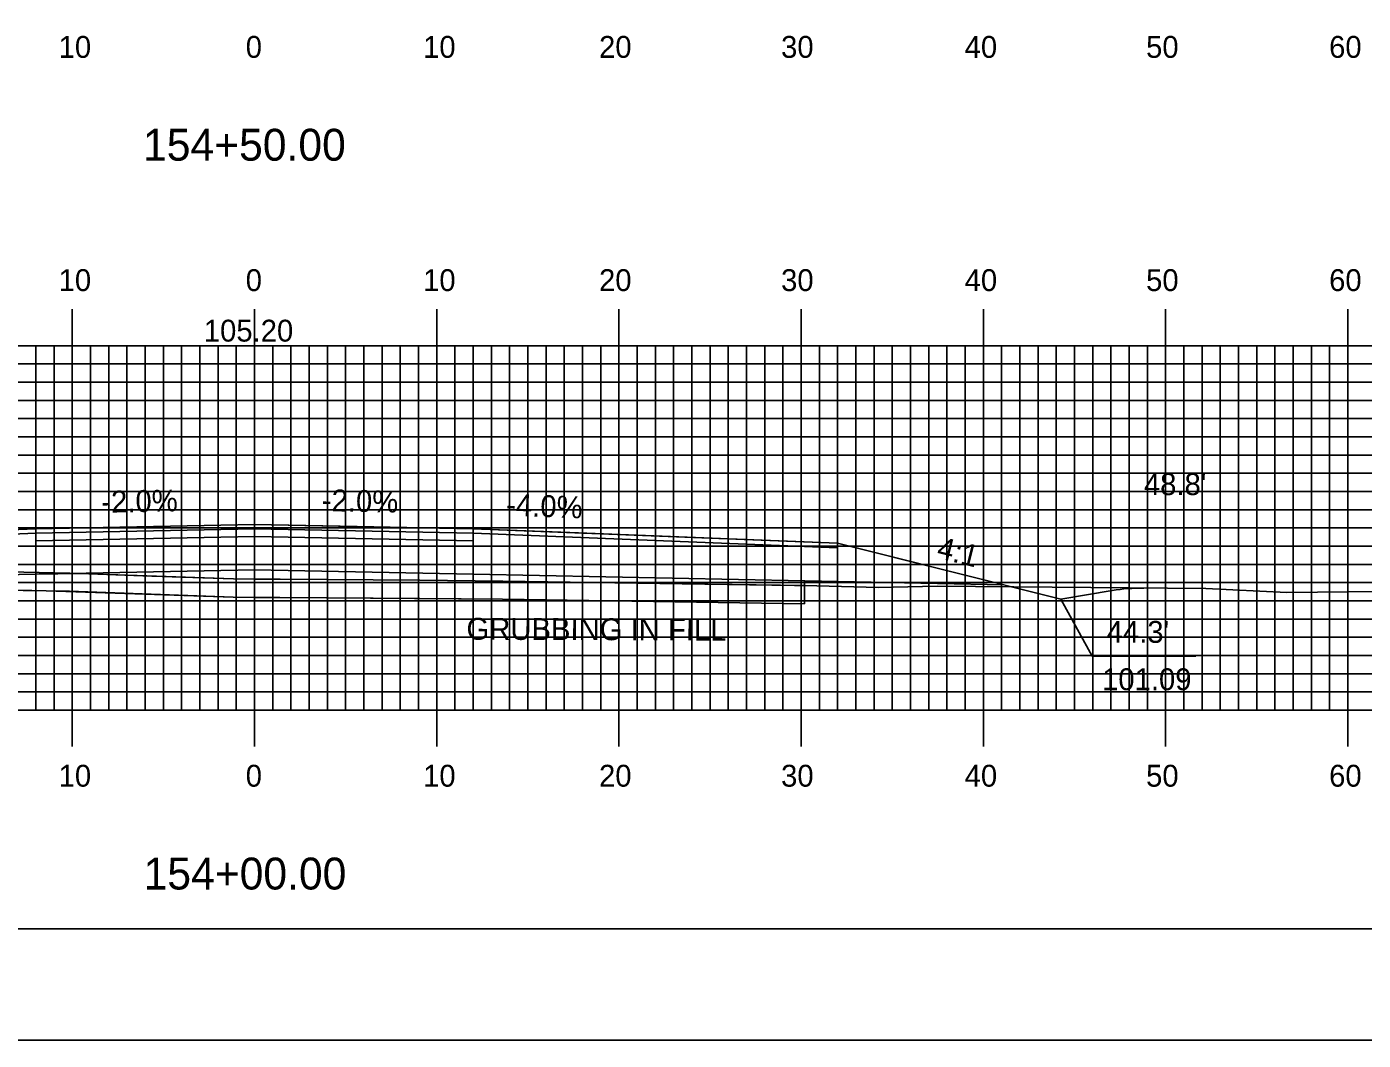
# Model space of a CAD drawing. Extents: x 1779106 to 1779449, y 442591 to 442811.
# Drawn here: x 1779258.8 to 1779332.2, y 442590.5 to 442646.2 of the extents above; entities that cross this region are included whole.
import ezdxf

# ---------------------------------------------------------------- set-up
doc = ezdxf.new("R2010")
doc.units = 0
for name, color, linetype in [('ANNOTATION', 7, 'Continuous'), ('BORDER', 7, 'Continuous'), ('D_Roadway_Centerline', 7, 'Continuous'), ('D_Roadway_Centerline_Text', 7, 'Continuous'), ('D_Roadway_Edge_Shoulder', 7, 'Continuous'), ('D_Roadway_Edge_TW', 7, 'Continuous'), ('D_Roadway_Pavement', 7, 'Continuous'), ('D_Roadway_SlopeLines', 7, 'Continuous'), ('D_Roadway_SubGrade', 7, 'Continuous'), ('D_Text_Standard', 7, 'Continuous'), ('GRUBBING IN FILL', 7, 'Continuous'), ('H_V ANNOTATION', 7, 'Continuous'), ('MAJOR', 7, 'Continuous'), ('MINOR', 7, 'Continuous'), ('PLOT BOUNDARY', 7, 'Continuous'), ('S_Roadway_Centerline', 7, 'Continuous')]:
    doc.layers.add(name, color=color, linetype=linetype)

msp = doc.modelspace()

# ---------------------------------------------------------------- linework, layer by layer
at = {"layer": 'ANNOTATION'}
msp.add_lwpolyline([(1779322.986, 442611.633), (1779317.295, 442611.633), (1779315.583, 442614.759)], dxfattribs=at)
at = {"layer": 'BORDER'}
msp.add_lwpolyline([(1779121.729, 442596.665), (1779441.729, 442596.665), (1779441.729, 442806.665), (1779121.729, 442806.665)], close=True, dxfattribs=at)
at = {"layer": 'D_Roadway_Centerline'}
msp.add_lwpolyline([(1779223.685, 442616.645), (1779224.433, 442616.615), (1779224.935, 442616.594), (1779225.68, 442616.537), (1779226.185, 442616.498), (1779227.435, 442616.357), (1779228.618, 442616.181), (1779228.685, 442616.171), (1779237.155, 442614.759), (1779241.156, 442615.759), (1779251.329, 442618.302), (1779259.329, 442618.622), (1779271.328, 442618.862), (1779271.329, 442618.862), (1779276.972, 442618.749), (1779283.329, 442618.622), (1779289.105, 442618.391), (1779303.329, 442617.822)], dxfattribs=at)
at = {"layer": 'D_Roadway_Edge_Shoulder'}
for points in [[(1779259.329, 442618.622), (1779251.329, 442618.302), (1779251.329, 442618.052), (1779259.329, 442618.372)], [(1779283.329, 442618.622), (1779303.329, 442617.822), (1779303.329, 442617.572), (1779283.329, 442618.372)]]:
    msp.add_lwpolyline(points, close=True, dxfattribs=at)
at = {"layer": 'D_Roadway_Edge_TW'}
msp.add_lwpolyline([(1779259.329, 442618.372), (1779259.329, 442618.622), (1779271.329, 442618.862), (1779283.329, 442618.622), (1779283.329, 442618.372), (1779271.329, 442618.612)], close=True, dxfattribs=at)
at = {"layer": 'D_Roadway_Pavement'}
msp.add_lwpolyline([(1779259.329, 442617.956), (1779259.329, 442618.372), (1779271.329, 442618.612), (1779283.329, 442618.372), (1779283.329, 442617.956), (1779271.329, 442618.196)], close=True, dxfattribs=at)
at = {"layer": 'D_Roadway_SlopeLines'}
msp.add_line((1779315.583, 442614.759), (1779318.398, 442615.228), dxfattribs=at)
msp.add_lwpolyline([(1779303.329, 442617.822), (1779315.583, 442614.759)], dxfattribs=at)
msp.add_arc((1779320.042, 442605.365), 10, 89.51014, 99.46232, dxfattribs=at)
at = {"layer": 'D_Roadway_SubGrade'}
msp.add_lwpolyline([(1779259.329, 442616.122), (1779241.156, 442615.759), (1779251.329, 442618.302), (1779251.329, 442618.052), (1779259.329, 442618.372), (1779271.329, 442618.612), (1779283.329, 442618.372), (1779303.329, 442617.572), (1779303.329, 442617.822), (1779312.457, 442615.54), (1779283.329, 442616.122), (1779271.329, 442616.362)], close=True, dxfattribs=at)
at = {"layer": 'GRUBBING IN FILL'}
msp.add_line((1779301.503, 442615.759), (1779301.503, 442614.502), dxfattribs=at)
msp.add_line((1779301.503, 442615.759), (1779301.503, 442614.502), dxfattribs=at)
for points in [[(1779241.156, 442615.759), (1779241.156, 442615.37), (1779248.552, 442615.339), (1779255.948, 442615.307), (1779259.904, 442615.212), (1779270.157, 442614.864), (1779271.329, 442614.856), (1779271.329, 442615.856), (1779270.179, 442615.864), (1779265.686, 442616.027), (1779261.743, 442616.17), (1779259.329, 442616.122), (1779250.242, 442615.941)], [(1779241.156, 442615.759), (1779241.156, 442615.37), (1779248.552, 442615.339), (1779255.948, 442615.307), (1779259.904, 442615.212), (1779270.157, 442614.864), (1779271.329, 442614.856), (1779271.329, 442615.856), (1779270.179, 442615.864), (1779265.686, 442616.027), (1779261.743, 442616.17), (1779259.329, 442616.122), (1779250.242, 442615.941)], [(1779271.329, 442615.856), (1779275.29, 442615.827), (1779280.401, 442615.791), (1779284.957, 442615.75), (1779293.576, 442615.621), (1779301.503, 442615.502), (1779301.503, 442614.502), (1779284.945, 442614.75), (1779275.275, 442614.828), (1779271.329, 442614.856)], [(1779271.329, 442615.856), (1779275.29, 442615.827), (1779280.401, 442615.791), (1779284.957, 442615.75), (1779293.576, 442615.621), (1779301.503, 442615.502), (1779301.503, 442614.502), (1779284.945, 442614.75), (1779275.275, 442614.828), (1779271.329, 442614.856)]]:
    msp.add_lwpolyline(points, close=True, dxfattribs=at)
msp.add_lwpolyline([(1779241.156, 442615.37), (1779255.948, 442615.307), (1779258.64, 442615.233), (1779261.168, 442615.191), (1779270.157, 442614.864), (1779280.393, 442614.791), (1779284.945, 442614.75), (1779301.503, 442614.502)], dxfattribs=at)
msp.add_lwpolyline([(1779241.156, 442615.37), (1779255.948, 442615.307), (1779258.64, 442615.233), (1779261.168, 442615.191), (1779270.157, 442614.864), (1779280.393, 442614.791), (1779284.945, 442614.75), (1779301.503, 442614.502)], dxfattribs=at)
at = {"layer": 'MAJOR'}
for p, q in [((1779261.329, 442630.669), (1779261.329, 442628.665)), ((1779271.329, 442630.669), (1779271.329, 442628.665)), ((1779281.329, 442630.669), (1779281.329, 442628.665)), ((1779291.329, 442630.669), (1779291.329, 442628.665)), ((1779301.329, 442630.669), (1779301.329, 442628.665)), ((1779311.329, 442630.669), (1779311.329, 442628.665)), ((1779321.329, 442630.669), (1779321.329, 442628.665)), ((1779331.329, 442630.669), (1779331.329, 442628.665)), ((1779131.329, 442628.665), (1779411.329, 442628.665)), ((1779131.329, 442628.665), (1779411.329, 442628.665)), ((1779261.329, 442608.665), (1779261.329, 442628.665)), ((1779271.329, 442608.665), (1779271.329, 442628.665)), ((1779281.329, 442608.665), (1779281.329, 442628.665)), ((1779291.329, 442608.665), (1779291.329, 442628.665)), ((1779301.329, 442608.665), (1779301.329, 442628.665)), ((1779311.329, 442608.665), (1779311.329, 442628.665)), ((1779321.329, 442608.665), (1779321.329, 442628.665)), ((1779331.329, 442608.665), (1779331.329, 442628.665)), ((1779131.329, 442623.665), (1779411.329, 442623.665)), ((1779131.329, 442618.665), (1779411.329, 442618.665)), ((1779131.329, 442613.665), (1779411.329, 442613.665)), ((1779131.329, 442608.665), (1779411.329, 442608.665)), ((1779131.329, 442608.665), (1779411.329, 442608.665)), ((1779261.329, 442606.661), (1779261.329, 442608.665)), ((1779271.329, 442606.661), (1779271.329, 442608.665)), ((1779281.329, 442606.661), (1779281.329, 442608.665)), ((1779291.329, 442606.661), (1779291.329, 442608.665)), ((1779301.329, 442606.661), (1779301.329, 442608.665)), ((1779311.329, 442606.661), (1779311.329, 442608.665)), ((1779321.329, 442606.661), (1779321.329, 442608.665)), ((1779331.329, 442606.661), (1779331.329, 442608.665))]:
    msp.add_line(p, q, dxfattribs=at)
at = {"layer": 'MINOR'}
for p, q in [((1779259.329, 442608.665), (1779259.329, 442628.665)), ((1779260.329, 442608.665), (1779260.329, 442628.665)), ((1779262.329, 442608.665), (1779262.329, 442628.665)), ((1779263.329, 442608.665), (1779263.329, 442628.665)), ((1779264.329, 442608.665), (1779264.329, 442628.665)), ((1779265.329, 442608.665), (1779265.329, 442628.665)), ((1779266.329, 442608.665), (1779266.329, 442628.665)), ((1779267.329, 442608.665), (1779267.329, 442628.665)), ((1779268.329, 442608.665), (1779268.329, 442628.665)), ((1779269.329, 442608.665), (1779269.329, 442628.665)), ((1779270.329, 442608.665), (1779270.329, 442628.665)), ((1779272.329, 442608.665), (1779272.329, 442628.665)), ((1779273.329, 442608.665), (1779273.329, 442628.665)), ((1779274.329, 442608.665), (1779274.329, 442628.665)), ((1779275.329, 442608.665), (1779275.329, 442628.665)), ((1779276.329, 442608.665), (1779276.329, 442628.665)), ((1779277.329, 442608.665), (1779277.329, 442628.665)), ((1779278.329, 442608.665), (1779278.329, 442628.665)), ((1779279.329, 442608.665), (1779279.329, 442628.665)), ((1779280.329, 442608.665), (1779280.329, 442628.665)), ((1779282.329, 442608.665), (1779282.329, 442628.665)), ((1779283.329, 442608.665), (1779283.329, 442628.665)), ((1779284.329, 442608.665), (1779284.329, 442628.665)), ((1779285.329, 442608.665), (1779285.329, 442628.665)), ((1779286.329, 442608.665), (1779286.329, 442628.665)), ((1779287.329, 442608.665), (1779287.329, 442628.665)), ((1779288.329, 442608.665), (1779288.329, 442628.665)), ((1779289.329, 442608.665), (1779289.329, 442628.665)), ((1779290.329, 442608.665), (1779290.329, 442628.665)), ((1779292.329, 442608.665), (1779292.329, 442628.665)), ((1779293.329, 442608.665), (1779293.329, 442628.665)), ((1779294.329, 442608.665), (1779294.329, 442628.665)), ((1779295.329, 442608.665), (1779295.329, 442628.665)), ((1779296.329, 442608.665), (1779296.329, 442628.665)), ((1779297.329, 442608.665), (1779297.329, 442628.665)), ((1779298.329, 442608.665), (1779298.329, 442628.665)), ((1779299.329, 442608.665), (1779299.329, 442628.665)), ((1779300.329, 442608.665), (1779300.329, 442628.665)), ((1779302.329, 442608.665), (1779302.329, 442628.665)), ((1779303.329, 442608.665), (1779303.329, 442628.665)), ((1779304.329, 442608.665), (1779304.329, 442628.665)), ((1779305.329, 442608.665), (1779305.329, 442628.665)), ((1779306.329, 442608.665), (1779306.329, 442628.665)), ((1779307.329, 442608.665), (1779307.329, 442628.665)), ((1779308.329, 442608.665), (1779308.329, 442628.665)), ((1779309.329, 442608.665), (1779309.329, 442628.665)), ((1779310.329, 442608.665), (1779310.329, 442628.665)), ((1779312.329, 442608.665), (1779312.329, 442628.665)), ((1779313.329, 442608.665), (1779313.329, 442628.665)), ((1779314.329, 442608.665), (1779314.329, 442628.665)), ((1779315.329, 442608.665), (1779315.329, 442628.665)), ((1779316.329, 442608.665), (1779316.329, 442628.665)), ((1779317.329, 442608.665), (1779317.329, 442628.665)), ((1779318.329, 442608.665), (1779318.329, 442628.665)), ((1779319.329, 442608.665), (1779319.329, 442628.665)), ((1779320.329, 442608.665), (1779320.329, 442628.665)), ((1779322.329, 442608.665), (1779322.329, 442628.665)), ((1779323.329, 442608.665), (1779323.329, 442628.665)), ((1779324.329, 442608.665), (1779324.329, 442628.665)), ((1779325.329, 442608.665), (1779325.329, 442628.665)), ((1779326.329, 442608.665), (1779326.329, 442628.665)), ((1779327.329, 442608.665), (1779327.329, 442628.665)), ((1779328.329, 442608.665), (1779328.329, 442628.665)), ((1779329.329, 442608.665), (1779329.329, 442628.665)), ((1779330.329, 442608.665), (1779330.329, 442628.665)), ((1779131.329, 442627.665), (1779411.329, 442627.665)), ((1779131.329, 442626.665), (1779411.329, 442626.665)), ((1779131.329, 442625.665), (1779411.329, 442625.665)), ((1779131.329, 442624.665), (1779411.329, 442624.665)), ((1779131.329, 442622.665), (1779411.329, 442622.665)), ((1779131.329, 442621.665), (1779411.329, 442621.665)), ((1779131.329, 442620.665), (1779411.329, 442620.665)), ((1779131.329, 442619.665), (1779411.329, 442619.665)), ((1779131.329, 442617.665), (1779411.329, 442617.665)), ((1779131.329, 442616.665), (1779411.329, 442616.665)), ((1779131.329, 442615.665), (1779411.329, 442615.665)), ((1779131.329, 442614.665), (1779411.329, 442614.665)), ((1779131.329, 442612.665), (1779411.329, 442612.665)), ((1779131.329, 442611.665), (1779411.329, 442611.665)), ((1779131.329, 442610.665), (1779411.329, 442610.665)), ((1779131.329, 442609.665), (1779411.329, 442609.665))]:
    msp.add_line(p, q, dxfattribs=at)
at = {"layer": 'PLOT BOUNDARY'}
msp.add_lwpolyline([(1779105.542, 442590.547), (1779445.542, 442590.547), (1779445.542, 442810.547), (1779105.542, 442810.547)], close=True, dxfattribs=at)
at = {"layer": 'S_Roadway_Centerline'}
msp.add_lwpolyline([(1779192.273, 442616.677), (1779209.36, 442616.778), (1779212.554, 442616.757), (1779223.258, 442616.655), (1779234.429, 442616.399), (1779237.508, 442616.386), (1779255.964, 442616.307), (1779258.662, 442616.233), (1779261.194, 442616.19), (1779270.179, 442615.864), (1779280.401, 442615.791), (1779284.957, 442615.75), (1779302.194, 442615.492), (1779305.57, 442615.393), (1779308.793, 442615.461), (1779323.543, 442615.335), (1779327.985, 442615.115), (1779346.563, 442615.325)], dxfattribs=at)

# ---------------------------------------------------------------- texts
at = {"layer": 'ANNOTATION'}
for s, rotation, p in [('-2.0%', 1.14572, (1779262.935, 442619.495)), ('-2.0%', 358.85424, (1779275.015, 442619.589)), ('-4.0%', 357.70927, (1779285.121, 442619.352)), ('4:1', 345.96596, (1779308.712, 442617.036))]:
    msp.add_text(s, height=1.2, rotation=rotation, dxfattribs=at).set_placement(p)
for s, p in [("44.3'", (1779318.094, 442612.36)), ('101.09', (1779317.842, 442609.76))]:
    msp.add_text(s, height=1.2, dxfattribs=at).set_placement(p)
at = {"layer": 'D_Roadway_Centerline'}
for s, p in [('C', (1779271.324, 442618.862)), ('L', (1779271.329, 442618.855))]:
    msp.add_text(s, height=0.0146, dxfattribs=at).set_placement(p)
at = {"layer": 'D_Roadway_Centerline_Text'}
msp.add_text('105.20', height=1.2, dxfattribs=at).set_placement((1779268.547, 442628.892))
at = {"layer": 'D_Text_Standard'}
msp.add_text("48.8'", height=1.2, dxfattribs=at).set_placement((1779320.137, 442620.467))
at = {"layer": 'GRUBBING IN FILL'}
msp.add_text('GRUBBING IN FILL', height=1.2, rotation=359.80532, dxfattribs=at).set_placement((1779282.96, 442612.53))
at = {"layer": 'H_V ANNOTATION'}
for s, height, p in [('10', 1.2, (1779260.58, 442644.465)), ('0', 1.2, (1779270.847, 442644.465)), ('10', 1.2, (1779280.58, 442644.465)), ('20', 1.2, (1779290.237, 442644.465)), ('30', 1.2, (1779300.227, 442644.465)), ('40', 1.2, (1779310.301, 442644.465)), ('50', 1.2, (1779320.258, 442644.465)), ('60', 1.2, (1779330.301, 442644.465)), ('154+50.00', 1.75, (1779265.212, 442638.821)), ('10', 1.2, (1779260.58, 442631.665)), ('0', 1.2, (1779270.847, 442631.665)), ('10', 1.2, (1779280.58, 442631.665)), ('20', 1.2, (1779290.237, 442631.665)), ('30', 1.2, (1779300.227, 442631.665)), ('40', 1.2, (1779310.301, 442631.665)), ('50', 1.2, (1779320.258, 442631.665)), ('60', 1.2, (1779330.301, 442631.665)), ('10', 1.2, (1779260.58, 442604.465)), ('0', 1.2, (1779270.847, 442604.465)), ('10', 1.2, (1779280.58, 442604.465)), ('20', 1.2, (1779290.237, 442604.465)), ('30', 1.2, (1779300.227, 442604.465)), ('40', 1.2, (1779310.301, 442604.465)), ('50', 1.2, (1779320.258, 442604.465)), ('60', 1.2, (1779330.301, 442604.465)), ('154+00.00', 1.75, (1779265.243, 442598.821))]:
    msp.add_text(s, height=height, dxfattribs=at).set_placement(p)

doc.saveas('drawing.dxf')
